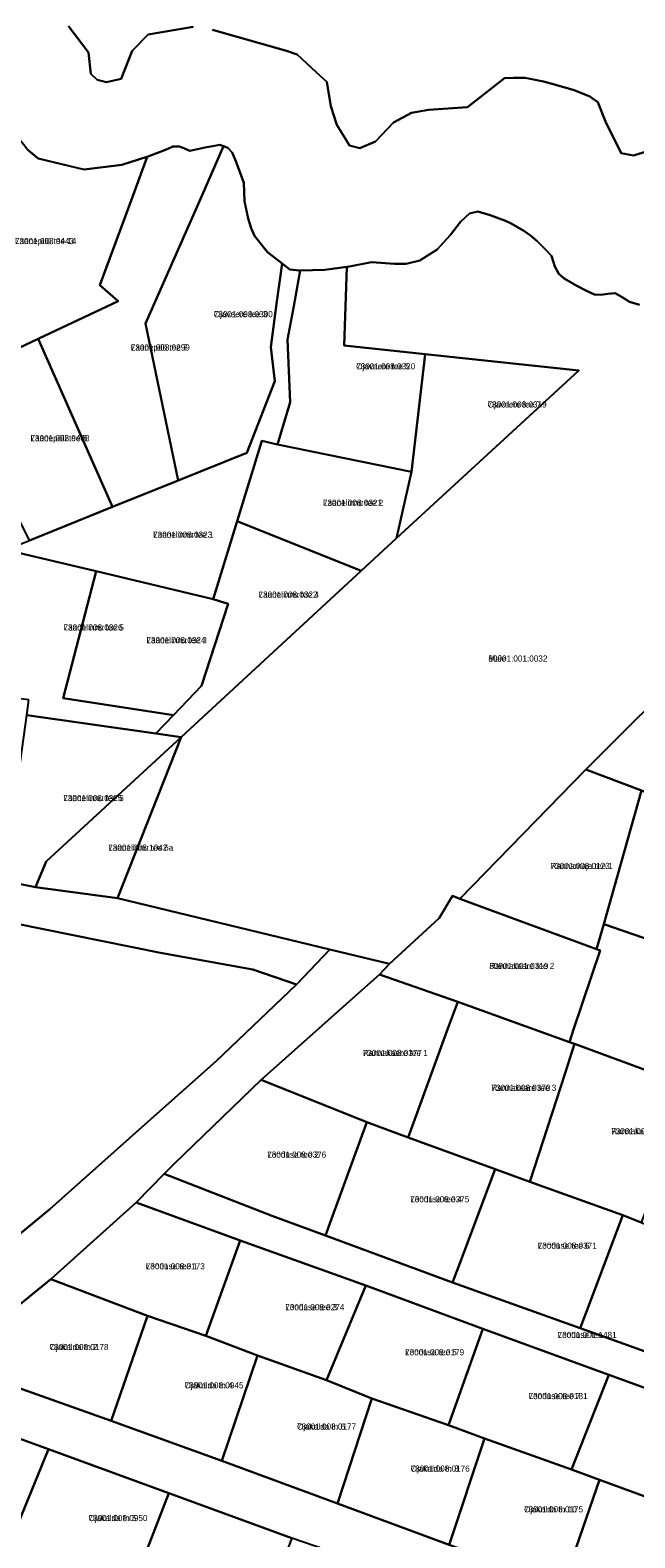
# Model space of a CAD drawing. Extents: x 524000 to 564260, y 6469338 to 6496391.
# Drawn here: x 535481.7 to 535630.3, y 6471654.6 to 6472024.8 of the extents above; entities that cross this region are included whole.
import ezdxf

# ---------------------------------------------------------------- set-up
doc = ezdxf.new("R2010")
doc.units = 0
for name, color, linetype in [('L_AADRESS', 7, 'Continuous'), ('PIIR', 7, 'Continuous'), ('TUNNUS', 7, 'Continuous')]:
    doc.layers.add(name, color=color, linetype=linetype)

msp = doc.modelspace()

# ---------------------------------------------------------------- linework, layer by layer
at = {"layer": 'PIIR'}
for points in [[(535521.75, 6472025.67), (535510.64, 6472023.76), (535506.78, 6472019.78), (535504.04, 6472012.85), (535500.41, 6472012.03), (535498.17, 6472012.59), (535496.6, 6472014.1), (535496.05, 6472019.34), (535491.1, 6472025.79)], [(535491.1, 6472025.79), (535496.05, 6472019.34), (535496.6, 6472014.1), (535498.17, 6472012.59), (535500.41, 6472012.03), (535504.04, 6472012.85), (535506.78, 6472019.78), (535510.64, 6472023.76), (535521.75, 6472025.67)], [(535643.7, 6471998.3), (535629.98, 6471994.08), (535626.93, 6471994.64), (535623.08, 6472002.43), (535621.18, 6472007.15), (535619.19, 6472008.54), (535615.39, 6472010.11), (535610.53, 6472011.46), (535607.82, 6472012.25), (535603.3, 6472013.16), (535600.36, 6472013.15), (535598.28, 6472013.07), (535589.18, 6472005.91), (535579.55, 6472005.24), (535575.39, 6472004.54), (535570.99, 6472002.17), (535566.56, 6471997.51), (535562.73, 6471995.86), (535560.19, 6471996.49), (535557.01, 6472001.57), (535555.58, 6472006.17), (535554.55, 6472012.1), (535552.97, 6472013.63), (535550.79, 6472015.61), (535547.33, 6472018.87), (535544.64, 6472019.76), (535526.52, 6472024.88)], [(535526.52, 6472024.88), (535544.64, 6472019.76), (535547.33, 6472018.87), (535550.79, 6472015.61), (535552.97, 6472013.63), (535554.55, 6472012.1), (535555.58, 6472006.17), (535557.01, 6472001.57), (535560.19, 6471996.49), (535562.73, 6471995.86), (535566.56, 6471997.51), (535570.99, 6472002.17), (535575.39, 6472004.54), (535579.55, 6472005.24), (535589.18, 6472005.91), (535598.28, 6472013.07), (535600.36, 6472013.15), (535603.3, 6472013.16), (535607.82, 6472012.25), (535610.53, 6472011.46), (535615.39, 6472010.11), (535619.19, 6472008.54), (535621.18, 6472007.15), (535623.08, 6472002.43), (535626.93, 6471994.64), (535629.98, 6471994.08), (535643.7, 6471998.3)], [(535631.46, 6471957.38), (535628.97, 6471958.13), (535627.14, 6471959.28), (535625.41, 6471960.25), (535623.61, 6471960.1), (535621.89, 6471959.84), (535620.39, 6471959.95), (535618.38, 6471960.85), (535616.05, 6471962.01), (535612.93, 6471963.82), (535611.61, 6471964.96), (535610.61, 6471966.83), (535609.76, 6471969.4), (535608.17, 6471971.15), (535606.25, 6471973.05), (535604.65, 6471974.37), (535602.99, 6471975.58), (535599.87, 6471977.37), (535598.48, 6471978.03), (535594.74, 6471979.38), (535591.67, 6471980.26), (535589.64, 6471979.78), (535587.42, 6471977.8), (535584.99, 6471974.6), (535581.67, 6471970.94), (535579.28, 6471969.45), (535577.42, 6471968.23), (535574.06, 6471967.46), (535571.2, 6471967.41), (535565.53, 6471967.82), (535559.78, 6471966.71), (535559.54, 6471966.68), (535554.06, 6471965.98), (535548.06, 6471965.81), (535547.94, 6471965.8), (535545.47, 6471966.02), (535543.58, 6471967.51), (535540, 6471970.33), (535536.78, 6471974.3), (535535.97, 6471976.22), (535535.27, 6471978.58), (535534.34, 6471982.82), (535534.17, 6471987.33), (535533.29, 6471989.78), (535532.19, 6471992.67), (535531.32, 6471994.81), (535530.22, 6471995.94), (535529.19, 6471996.32), (535528.3, 6471996.64), (535524.67, 6471995.98), (535520.95, 6471995.19), (535519.64, 6471995.76), (535518.37, 6471996.29), (535516.75, 6471996.28), (535515.35, 6471995.63), (535510.46, 6471993.73), (535510.35, 6471993.69), (535504.22, 6471991.78), (535494.93, 6471990.61), (535493.84, 6471990.88), (535483.66, 6471993.35), (535481.19, 6471995.34)], [(535645.1, 6471870.01), (535618.25, 6471843.27), (535587.31, 6471811.54), (535585.5, 6471812.27), (535582.16, 6471806.79), (535569.95, 6471795.52), (535555.36, 6471799.05), (535503.14, 6471811.67), (535518.8, 6471851.23), (535563, 6471892.08), (535571.72, 6471900.12), (535616.48, 6471941.26), (535578.77, 6471945.28), (535558.83, 6471947.42), (535559.36, 6471961.8), (535559.54, 6471966.68), (535559.78, 6471966.71), (535565.53, 6471967.82), (535571.2, 6471967.41), (535574.06, 6471967.46), (535577.42, 6471968.23), (535579.28, 6471969.45), (535581.67, 6471970.94), (535584.99, 6471974.6), (535587.42, 6471977.8), (535589.64, 6471979.78), (535591.67, 6471980.26), (535594.74, 6471979.38), (535598.48, 6471978.03), (535599.87, 6471977.37), (535602.99, 6471975.58), (535604.65, 6471974.37), (535606.25, 6471973.05), (535608.17, 6471971.15), (535609.76, 6471969.4), (535610.61, 6471966.83), (535611.61, 6471964.96), (535612.93, 6471963.82), (535616.05, 6471962.01), (535618.38, 6471960.85), (535620.39, 6471959.95), (535621.89, 6471959.84), (535623.61, 6471960.1), (535625.41, 6471960.25), (535627.14, 6471959.28), (535628.97, 6471958.13), (535631.46, 6471957.38)], [(535475.2, 6471815.95), (535482.97, 6471814.41), (535503.14, 6471811.67), (535555.36, 6471799.05), (535547.13, 6471790.52), (535536.44, 6471794.16), (535513.7, 6471798.28), (535470.71, 6471806.96)], [(535334.13, 6471643.54), (535432.3, 6471696.1), (535442.91, 6471701.88), (535455.01, 6471709.82), (535465.7, 6471718.2), (535486.55, 6471735.35), (535509.9, 6471756.13), (535527.35, 6471771.63), (535547.13, 6471790.52), (535555.36, 6471799.05), (535569.95, 6471795.52), (535567.53, 6471792.92), (535561.63, 6471787.68), (535538.42, 6471767.1), (535517.16, 6471746.52), (535514.57, 6471744.01), (535507.72, 6471736.91), (535486.72, 6471718.11), (535461.42, 6471697.61), (535447.79, 6471690.25), (535407.58, 6471668.53), (535385.87, 6471656.69), (535380.64, 6471653.45)], [(535636.37, 6471622.1), (535605.99, 6471633.1), (535575.78, 6471644.26), (535545.95, 6471654.54), (535515.72, 6471665.59), (535486.15, 6471676.39), (535455.47, 6471687.48), (535447.79, 6471690.25), (535461.42, 6471697.61), (535501.62, 6471683.31), (535528.82, 6471673.51), (535557.22, 6471663.01), (535584.62, 6471652.91), (535612.62, 6471642.71), (535639.99, 6471632.87)]]:
    msp.add_lwpolyline(points, dxfattribs=at)
for points in [[(535451.41, 6471976.33), (535459.83, 6471980.9), (535473.53, 6472000.07), (535475.51, 6472002.85), (535475.63, 6472002.7), (535477.98, 6471999.46), (535481.19, 6471995.34), (535483.66, 6471993.35), (535494.93, 6471990.61), (535504.22, 6471991.78), (535510.35, 6471993.69), (535510.46, 6471993.73), (535506.97, 6471984.28), (535498.81, 6471962.19), (535503.27, 6471958.31), (535483.63, 6471949.06), (535468.16, 6471941.73)], [(535503.27, 6471958.31), (535498.81, 6471962.19), (535506.97, 6471984.28), (535510.46, 6471993.73), (535515.35, 6471995.63), (535516.75, 6471996.28), (535518.37, 6471996.29), (535519.64, 6471995.76), (535520.95, 6471995.19), (535524.67, 6471995.98), (535528.3, 6471996.64), (535529.19, 6471996.32), (535523.92, 6471984.34), (535510.03, 6471952.76), (535518.07, 6471914.26), (535501.89, 6471907.74), (535483.63, 6471949.06)], [(535510.03, 6471952.76), (535523.92, 6471984.34), (535529.19, 6471996.32), (535530.22, 6471995.94), (535531.32, 6471994.81), (535532.19, 6471992.67), (535533.29, 6471989.78), (535534.17, 6471987.33), (535534.34, 6471982.82), (535535.27, 6471978.58), (535535.97, 6471976.22), (535536.78, 6471974.3), (535540, 6471970.33), (535543.58, 6471967.51), (535542.24, 6471957.64), (535540.8, 6471946.95), (535541.83, 6471938.63), (535534.94, 6471921.06), (535518.07, 6471914.26)], [(535475.74, 6471897.2), (535481.49, 6471899.51), (535501.89, 6471907.74), (535518.07, 6471914.26), (535534.94, 6471921.06), (535541.83, 6471938.63), (535540.8, 6471946.95), (535542.24, 6471957.64), (535543.58, 6471967.51), (535545.47, 6471966.02), (535547.94, 6471965.8), (535548.06, 6471965.81), (535546.44, 6471957.03), (535544.93, 6471948.84), (535545.58, 6471933.49), (535542.46, 6471923.1), (535538.64, 6471923.99), (535532.58, 6471904.27), (535526.64, 6471885.13), (535497.9, 6471891.94)], [(535545.58, 6471933.49), (535544.93, 6471948.84), (535546.44, 6471957.03), (535548.06, 6471965.81), (535554.06, 6471965.98), (535559.54, 6471966.68), (535559.36, 6471961.8), (535558.83, 6471947.42), (535578.77, 6471945.28), (535575.42, 6471916.37), (535542.46, 6471923.1)], [(535461.61, 6471939.34), (535468.16, 6471941.73), (535483.63, 6471949.06), (535501.89, 6471907.74), (535481.49, 6471899.51)], [(535578.77, 6471945.28), (535616.48, 6471941.26), (535571.72, 6471900.12), (535575.42, 6471916.37)], [(535538.64, 6471923.99), (535542.46, 6471923.1), (535575.42, 6471916.37), (535571.72, 6471900.12), (535563, 6471892.08), (535532.58, 6471904.27)], [(535512.6, 6471852.09), (535516.94, 6471856.63), (535523.79, 6471863.79), (535530.34, 6471883.95), (535526.64, 6471885.13), (535532.58, 6471904.27), (535563, 6471892.08), (535518.8, 6471851.23)], [(535481.33, 6471860.37), (535462.81, 6471862.56), (535470.27, 6471894.99), (535475.74, 6471897.2), (535497.9, 6471891.94), (535489.83, 6471860.81), (535516.94, 6471856.63), (535512.6, 6471852.09), (535480.84, 6471856.61)], [(535497.9, 6471891.94), (535526.64, 6471885.13), (535530.34, 6471883.95), (535523.79, 6471863.79), (535516.94, 6471856.63), (535489.83, 6471860.81)], [(535618.25, 6471843.27), (535645.1, 6471870.01), (535670.4, 6471861.09), (535658.41, 6471828.12), (535631.89, 6471838.12)], [(535482.97, 6471814.41), (535475.2, 6471815.95), (535480.84, 6471856.61), (535512.6, 6471852.09), (535518.8, 6471851.23), (535485.63, 6471820.66)], [(535518.8, 6471851.23), (535503.14, 6471811.67), (535482.97, 6471814.41), (535485.63, 6471820.66)], [(535618.25, 6471843.27), (535631.89, 6471838.12), (535622.66, 6471805.31), (535620.85, 6471799.15), (535587.31, 6471811.54)], [(535631.89, 6471838.12), (535658.41, 6471828.12), (535660.21, 6471827.44), (535651.39, 6471795.36), (535622.66, 6471805.31)], [(535586.76, 6471786.23), (535567.53, 6471792.92), (535569.95, 6471795.52), (535582.16, 6471806.79), (535585.5, 6471812.27), (535587.31, 6471811.54), (535621.78, 6471798.81), (535615.23, 6471779.47), (535614.18, 6471776.32)], [(535547.13, 6471790.52), (535527.35, 6471771.63), (535509.9, 6471756.13), (535486.55, 6471735.35), (535465.7, 6471718.2), (535453.69, 6471738.52), (535419.25, 6471718.18), (535432.3, 6471696.1), (535334.13, 6471643.54), (535340.59, 6471671.9), (535353.8, 6471729.6), (535367.62, 6471737.37), (535427.17, 6471768.76), (535446.07, 6471783.63), (535469.52, 6471805.29), (535470.71, 6471806.96), (535513.7, 6471798.28), (535536.44, 6471794.16)], [(535614.18, 6471776.32), (535615.23, 6471779.47), (535621.78, 6471798.81), (535620.85, 6471799.15), (535622.66, 6471805.31), (535651.39, 6471795.36), (535643.22, 6471765.66), (535615.44, 6471775.87)], [(535538.42, 6471767.1), (535561.63, 6471787.68), (535567.53, 6471792.92), (535586.76, 6471786.23), (535584.34, 6471779.67), (535574.6, 6471752.93), (535564.39, 6471756.68)], [(535584.34, 6471779.67), (535586.76, 6471786.23), (535614.18, 6471776.32), (535615.44, 6471775.87), (535613.13, 6471768.74), (535604.48, 6471742.02), (535595.98, 6471745.12), (535574.6, 6471752.93)], [(535613.13, 6471768.74), (535615.44, 6471775.87), (535643.22, 6471765.66), (535644.46, 6471765.2), (535631.87, 6471732.03), (535627.32, 6471733.86), (535604.48, 6471742.02)], [(535514.57, 6471744.01), (535517.16, 6471746.52), (535538.42, 6471767.1), (535564.39, 6471756.68), (535555.66, 6471732.68), (535554.26, 6471728.83), (535541.32, 6471733.59)], [(535555.66, 6471732.68), (535564.39, 6471756.68), (535574.6, 6471752.93), (535595.98, 6471745.12), (535586.95, 6471721.15), (535585.5, 6471717.32), (535554.26, 6471728.83)], [(535507.72, 6471736.91), (535514.57, 6471744.01), (535541.32, 6471733.59), (535554.26, 6471728.83), (535585.5, 6471717.32), (535616.85, 6471706.08), (535648.75, 6471694.61), (535680.13, 6471683.17), (535712.37, 6471670.88), (535711.96, 6471669.44), (535710.26, 6471663.34), (535681.34, 6471673.74), (535651.62, 6471684.57), (535623.92, 6471694.61), (535592.92, 6471705.91), (535564.19, 6471716.55), (535533.3, 6471727.61)], [(535586.95, 6471721.15), (535595.98, 6471745.12), (535604.48, 6471742.02), (535627.32, 6471733.86), (535618.29, 6471709.92), (535616.85, 6471706.08), (535585.5, 6471717.32)], [(535486.72, 6471718.11), (535507.72, 6471736.91), (535533.3, 6471727.61), (535524.84, 6471704.2), (535510.52, 6471709.11)], [(535618.29, 6471709.92), (535627.32, 6471733.86), (535631.87, 6471732.03), (535658.85, 6471722.08), (535650.06, 6471698.49), (535648.75, 6471694.61), (535616.85, 6471706.08)], [(535533.3, 6471727.61), (535564.19, 6471716.55), (535554.49, 6471693.36), (535537.53, 6471699.35), (535524.84, 6471704.2)], [(535486.72, 6471718.11), (535510.52, 6471709.11), (535501.62, 6471683.31), (535461.42, 6471697.61)], [(535554.49, 6471693.36), (535564.19, 6471716.55), (535592.92, 6471705.91), (535584.52, 6471682.31), (535565.62, 6471688.81)], [(535510.52, 6471709.11), (535524.84, 6471704.2), (535537.53, 6471699.35), (535528.82, 6471673.51), (535501.62, 6471683.31)], [(535584.52, 6471682.31), (535592.92, 6471705.91), (535623.92, 6471694.61), (535614.72, 6471671.41), (535593.32, 6471679.01)], [(535537.53, 6471699.35), (535554.49, 6471693.36), (535565.62, 6471688.81), (535557.22, 6471663.01), (535528.82, 6471673.51)], [(535614.72, 6471671.41), (535623.92, 6471694.61), (535651.62, 6471684.57), (535643.31, 6471660.9), (535621.6, 6471668.85)], [(535455.47, 6471687.48), (535486.15, 6471676.39), (535476.16, 6471651.91), (535446.08, 6471662.8)], [(535565.62, 6471688.81), (535584.52, 6471682.31), (535593.32, 6471679.01), (535584.62, 6471652.91), (535557.22, 6471663.01)], [(535486.15, 6471676.39), (535515.72, 6471665.59), (535506.24, 6471641.03), (535476.16, 6471651.91)], [(535593.32, 6471679.01), (535614.72, 6471671.41), (535621.6, 6471668.85), (535612.62, 6471642.71), (535584.62, 6471652.91)], [(535621.6, 6471668.85), (535643.31, 6471660.9), (535649.15, 6471658.62), (535639.99, 6471632.87), (535612.62, 6471642.71)], [(535515.72, 6471665.59), (535545.95, 6471654.54), (535536.51, 6471630.12), (535506.24, 6471641.03)]]:
    msp.add_lwpolyline(points, close=True, dxfattribs=at)

# ---------------------------------------------------------------- texts
at = {"layer": 'L_AADRESS'}
for s, p in [('Laanepüü tee 14', (535477.95, 6471972.29)), ('Ojaveere tee 3', (535526.8, 6471954.34)), ('Laanepüü tee 7', (535506.41, 6471946.16)), ('Ojaveere tee 5', (535561.79, 6471941.53)), ('Ojaveere tee 7', (535594.1, 6471932.17)), ('Laanepüü tee 5', (535481.75, 6471923.89)), ('Laanelinnu tee 2', (535553.63, 6471908.03)), ('Laanelinnu tee 1', (535511.9, 6471900.2)), ('Laanelinnu tee 4', (535537.8, 6471885.48)), ('Laanelinnu tee 5', (535489.88, 6471877.41)), ('Laanelinnu tee 3', (535510.26, 6471874.29)), ('Maie', (535594.29, 6471869.78)), ('Laanelinnu tee 6', (535489.83, 6471835.51)), ('Laanelinnu tee 6a', (535500.88, 6471823.35)), ('Rannamaja tee 1', (535609.6, 6471818.85)), ('Rannakaare tee 2', (535594.53, 6471794.29)), ('Rannakaare tee 1', (535563.44, 6471772.93)), ('Rannakaare tee 3', (535595.02, 6471764.36)), ('Rannakaare tee 5', (535624.47, 6471753.71)), ('Looduse tee 2', (535539.94, 6471747.96)), ('Looduse tee 4', (535575.08, 6471737)), ('Looduse tee 6', (535606.42, 6471725.6)), ('Looduse tee 1', (535510.1, 6471720.55)), ('Looduse tee 3', (535544.38, 6471710.49)), ('Ojakalda tn 2', (535486.43, 6471700.71)), ('Looduse tee', (535611.3, 6471703.68)), ('Looduse tee 5', (535573.82, 6471699.43)), ('Ojakalda tn 4', (535519.6, 6471691.31)), ('Looduse tee 7', (535604.17, 6471688.66)), ('Ojakalda tn 6', (535547.27, 6471681.18)), ('Ojakalda tn 8', (535575.19, 6471670.86)), ('Ojakalda tn 10', (535603.06, 6471660.86)), ('Ojakalda tn 5', (535496, 6471658.71))]:
    msp.add_text(s, height=1.5, dxfattribs=at).set_placement(p)
at = {"layer": 'TUNNUS'}
for s, p in [('73001:008:0443', (535477.95, 6471972.29)), ('73001:008:0300', (535526.8, 6471954.34)), ('73001:008:0299', (535506.41, 6471946.16)), ('73001:008:0320', (535561.79, 6471941.53)), ('73001:008:0319', (535594.1, 6471932.17)), ('73001:008:0408', (535481.75, 6471923.89)), ('73001:008:0321', (535553.63, 6471908.03)), ('73001:008:0323', (535511.9, 6471900.2)), ('73001:008:0322', (535537.8, 6471885.48)), ('73001:008:0326', (535489.88, 6471877.41)), ('73001:008:0324', (535510.26, 6471874.29)), ('80901:001:0032', (535594.29, 6471869.78)), ('73001:008:0325', (535489.83, 6471835.51)), ('73001:008:1042', (535500.88, 6471823.35)), ('73001:008:0123', (535609.6, 6471818.85)), ('80901:001:0319', (535594.53, 6471794.29)), ('73001:008:0377', (535563.44, 6471772.93)), ('73001:008:0370', (535595.02, 6471764.36)), ('73001:008:0369', (535624.47, 6471753.71)), ('73001:008:0376', (535539.94, 6471747.96)), ('73001:008:0375', (535575.08, 6471737)), ('73001:008:0371', (535606.42, 6471725.6)), ('73001:008:0173', (535510.1, 6471720.55)), ('73001:008:0274', (535544.38, 6471710.49)), ('73001:008:0178', (535486.43, 6471700.71)), ('73001:001:1481', (535611.3, 6471703.68)), ('73001:008:0179', (535573.82, 6471699.43)), ('73001:008:0945', (535519.6, 6471691.31)), ('73001:008:0181', (535604.17, 6471688.66)), ('73001:008:0177', (535547.27, 6471681.18)), ('73001:008:0176', (535575.19, 6471670.86)), ('73001:008:0175', (535603.06, 6471660.86)), ('73001:008:0950', (535496, 6471658.71))]:
    msp.add_text(s, height=1.5, dxfattribs=at).set_placement(p)

doc.saveas('drawing.dxf')
